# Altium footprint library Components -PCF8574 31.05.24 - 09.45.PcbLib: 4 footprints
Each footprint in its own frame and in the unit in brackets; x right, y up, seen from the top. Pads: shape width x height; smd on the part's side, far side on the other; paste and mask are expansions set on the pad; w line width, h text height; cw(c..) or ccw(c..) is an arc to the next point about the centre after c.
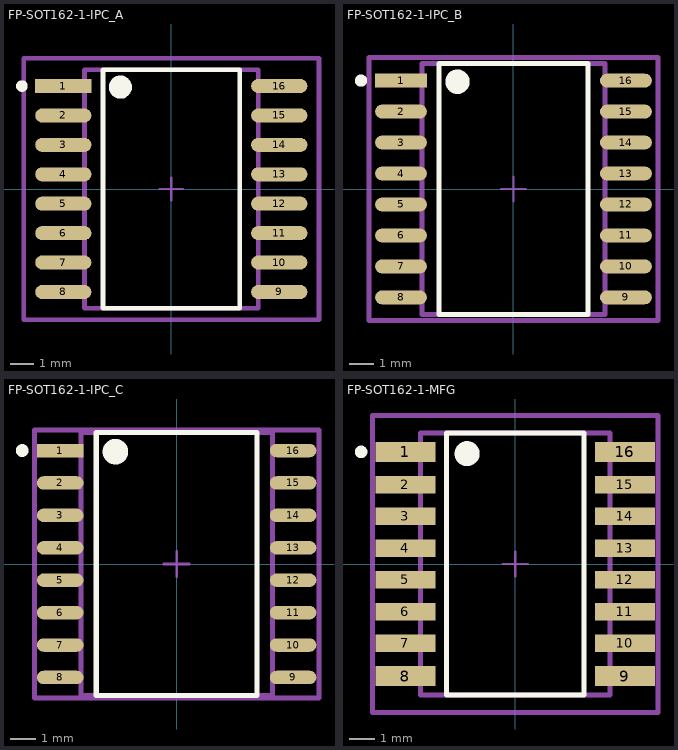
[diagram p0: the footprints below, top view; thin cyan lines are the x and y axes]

## FP-SOT162-1-IPC_A [mm]
pads (16):
  rect 2.428x0.608 smd paste+0 mask+0: 1(-4.663,4.445)
  rrect100% 2.428x0.608 smd paste+0 mask+0: 2(-4.663,3.175) 3(-4.663,1.905) 4(-4.663,0.635) 5(-4.663,-0.635) 6(-4.663,-1.905) 7(-4.663,-3.175) 8(-4.663,-4.445) 9(4.663,-4.445) 10(4.663,-3.175) 11(4.663,-1.905) 12(4.663,-0.635) 13(4.663,0.635) 14(4.663,1.905) 15(4.663,3.175) 16(4.663,4.445)
Top Overlay:
  circle w0.5: c-2.199,4.4 r0.25
  circle w0.25: c-6.452,4.445 r0.125
  lines w0.2: -2.949,-5.15 2.949,-5.15 2.949,5.15 -2.949,5.15 -2.949,-5.15
Top Assembly:
  lines w0.2: -6.377,-5.65 6.377,-5.65 6.377,5.65 -6.377,5.65 -6.377,-5.65
  text ".Designator" at 0,0.188 h1
Top 3D Body:
  lines w0.2: -3.75,-5.15 3.75,-5.15 3.75,5.15 -3.75,5.15 -3.75,-5.15
Top Courtyard:
  lines w0.2: -6.377,-5.65 6.377,-5.65 6.377,5.65 -6.377,5.65 -6.377,-5.65
Top Component Center:
  lines w0.1: -0.5,0 0.5,0 ; 0,-0.5 0,0.5
3D body "IC_NXP_Semiconductors_PCF8574AT-3_518_eec.STEP": height 0.25, standoff 0, extent -6.377,-5.65 6.377,5.65

## FP-SOT162-1-IPC_B [mm]
pads (16):
  rect 2.128x0.568 smd paste+0 mask+0: 1(-4.613,4.445)
  rrect100% 2.128x0.568 smd paste+0 mask+0: 2(-4.613,3.175) 3(-4.613,1.905) 4(-4.613,0.635) 5(-4.613,-0.635) 6(-4.613,-1.905) 7(-4.613,-3.175) 8(-4.613,-4.445) 9(4.613,-4.445) 10(4.613,-3.175) 11(4.613,-1.905) 12(4.613,-0.635) 13(4.613,0.635) 14(4.613,1.905) 15(4.613,3.175) 16(4.613,4.445)
Top Overlay:
  circle w0.5: c-2.299,4.4 r0.25
  circle w0.25: c-6.252,4.445 r0.125
  lines w0.2: -3.049,-5.15 3.049,-5.15 3.049,5.15 -3.049,5.15 -3.049,-5.15
Top Assembly:
  lines w0.2: -5.927,-5.4 5.927,-5.4 5.927,5.4 -5.927,5.4 -5.927,-5.4
  text ".Designator" at 0,0.188 h1
Top 3D Body:
  lines w0.2: -3.75,-5.15 3.75,-5.15 3.75,5.15 -3.75,5.15 -3.75,-5.15
Top Courtyard:
  lines w0.2: -5.927,-5.4 5.927,-5.4 5.927,5.4 -5.927,5.4 -5.927,-5.4
Top Component Center:
  lines w0.1: -0.5,0 0.5,0 ; 0,-0.5 0,0.5
3D body "IC_NXP_Semiconductors_PCF8574AT-3_518_eec.STEP": height 0.25, standoff 0, extent -5.927,-5.4 5.927,5.4

## FP-SOT162-1-IPC_C [mm]
pads (16):
  rect 1.828x0.528 smd paste+0 mask+0: 1(-4.563,4.445)
  rrect100% 1.828x0.528 smd paste+0 mask+0: 2(-4.563,3.175) 3(-4.563,1.905) 4(-4.563,0.635) 5(-4.563,-0.635) 6(-4.563,-1.905) 7(-4.563,-3.175) 8(-4.563,-4.445) 9(4.563,-4.445) 10(4.563,-3.175) 11(4.563,-1.905) 12(4.563,-0.635) 13(4.563,0.635) 14(4.563,1.905) 15(4.563,3.175) 16(4.563,4.445)
Top Overlay:
  circle w0.5: c-2.399,4.4 r0.25
  circle w0.25: c-6.052,4.445 r0.125
  lines w0.2: -3.149,-5.15 3.149,-5.15 3.149,5.15 -3.149,5.15 -3.149,-5.15
Top Assembly:
  lines w0.2: -5.577,-5.25 5.577,-5.25 5.577,5.25 -5.577,5.25 -5.577,-5.25
  text ".Designator" at 0,0.188 h1
Top 3D Body:
  lines w0.2: -3.75,-5.15 3.75,-5.15 3.75,5.15 -3.75,5.15 -3.75,-5.15
Top Courtyard:
  lines w0.2: -5.577,-5.25 5.577,-5.25 5.577,5.25 -5.577,5.25 -5.577,-5.25
Top Component Center:
  lines w0.1: -0.5,0 0.5,0 ; 0,-0.5 0,0.5
3D body "IC_NXP_Semiconductors_PCF8574AT-3_518_eec.STEP": height 0.25, standoff 0, extent -5.577,-5.25 5.577,5.25

## FP-SOT162-1-MFG [mm]
pads (16):
  rect 2.4x0.8 smd paste+0 mask+0: 1(-4.4,4.495) 8(-4.4,-4.495) 9(4.4,-4.495) 16(4.4,4.495)
  rect 2.4x0.7 smd paste+0 mask+0: 2(-4.4,3.175) 3(-4.4,1.905) 4(-4.4,0.635) 5(-4.4,-0.635) 6(-4.4,-1.905) 7(-4.4,-3.175) 10(4.4,-3.175) 11(4.4,-1.905) 12(4.4,-0.635) 13(4.4,0.635) 14(4.4,1.905) 15(4.4,3.175)
Top Overlay:
  circle w0.25: c-6.175,4.495 r0.125
  circle w0.5: c-1.925,4.425 r0.25
  lines w0.2: -2.75,-5.25 2.75,-5.25 2.75,5.25 -2.75,5.25 -2.75,-5.25
Top Assembly:
  lines w0.2: -5.725,-5.95 5.725,-5.95 5.725,5.95 -5.725,5.95 -5.725,-5.95
  text ".Designator" at 0,0.188 h1
Top 3D Body:
  lines w0.2: -3.8,-5.25 3.8,-5.25 3.8,5.25 -3.8,5.25 -3.8,-5.25
Top Courtyard:
  lines w0.2: -5.725,-5.95 5.725,-5.95 5.725,5.95 -5.725,5.95 -5.725,-5.95
Top Component Center:
  lines w0.1: -0.5,0 0.5,0 ; 0,-0.5 0,0.5
3D body "IC_NXP_Semiconductors_PCF8574AT-3_518_eec.STEP": height 0.25, standoff 0, extent -5.725,-5.95 5.725,5.95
